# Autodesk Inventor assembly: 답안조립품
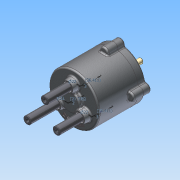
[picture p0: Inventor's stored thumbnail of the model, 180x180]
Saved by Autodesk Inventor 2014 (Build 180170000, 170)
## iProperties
Created: 2015-09
Part Number: 답안조립품
Document SubType Name: Assembly
Designer: study
Author: study
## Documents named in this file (14)
- C:\Users\study\Desktop\350916V1021\답안조립품.iam
- C:\Users\study\Desktop\350916V1021\몸체.ipt
- C:\Users\study\Desktop\350916V1021\M5x0.8x20.ipt
- C:\Users\study\Desktop\350916V1021\오일실.ipt
- C:\Users\study\Desktop\350916V1021\커버.ipt
- C:\Users\study\Desktop\350916V1021\멈춤링 22 x 1.2.ipt
- C:\Users\study\Desktop\350916V1021\메인 축.ipt
- C:\Users\study\Desktop\350916V1021\베어링 NA 4900.ipt
- C:\Users\study\Desktop\350916V1021\멈춤링 10 x 1.ipt
- C:\Users\study\Desktop\350916V1021\슬라이드 축.ipt
- C:\Users\study\Desktop\350916V1021\판캠.ipt
- C:\Users\study\Desktop\350916V1021\가변스프링1.ipt
- C:\Users\study\Desktop\350916V1021\가변스프링2.ipt
- C:\Users\study\Desktop\350916V1021\가변스프링3.ipt
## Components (7 placed, 4 different names)
1. 가변스프링1:1
2. 가변스프링2:1
3. 가변스프링3:1
4. M5x0.8x20:3
5. M5x0.8x20:4
6. M5x0.8x20:5
7. M5x0.8x20:6
